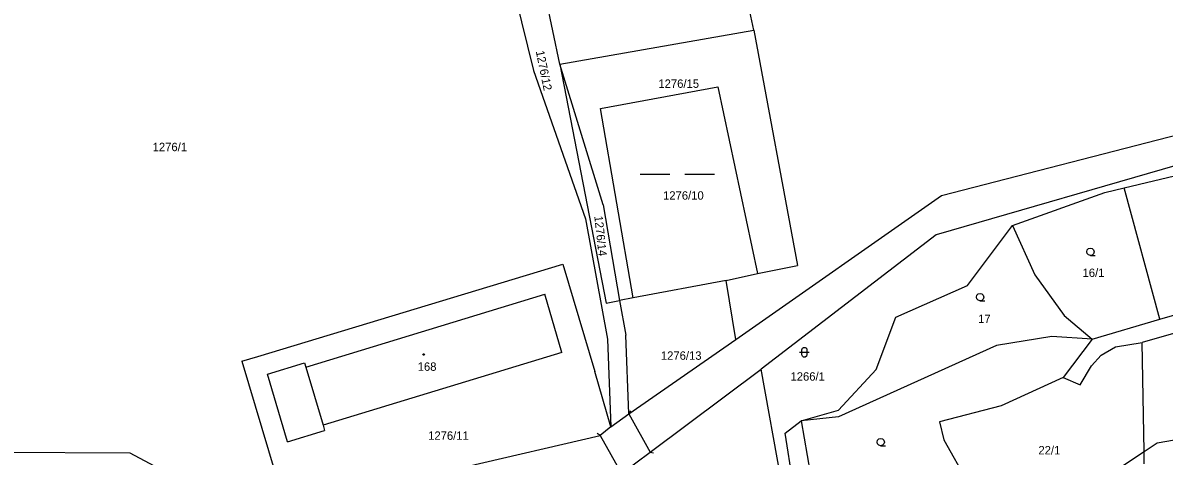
# Model space of a CAD drawing. Extents: x -799786 to -795190, y -1021716 to -1017834.
# Drawn here: x -798278.5 to -798047.9, y -1019024.7 to -1018937.1 of the extents above; entities that cross this region are included whole.
import ezdxf

# ---------------------------------------------------------------- set-up
doc = ezdxf.new("R2010")
doc.units = 0
for name, color, linetype in [('Default', 7, 'Continuous'), ('KN_HRANICE', 7, 'Continuous'), ('KN_KULTURY', 7, 'Continuous'), ('KN_PARCELY', 7, 'Continuous'), ('KN_SLUCKY', 7, 'Continuous')]:
    doc.layers.add(name, color=color, linetype=linetype)

# ---------------------------------------------------------------- blocks, each defined once
blk = doc.blocks.new('304')
at = {"layer": 'Default'}
blk.add_lwpolyline([(0, 0), (-0.38, 0.1), (-0.65, 0.37), (-0.75, 0.74), (-0.65, 1.11), (-0.38, 1.38), (-0.01, 1.48), (0.36, 1.38), (0.63, 1.11), (0.73, 0.73), (0.63, 0.35), (0.36, 0.08), (-0.02, -0.02), (0.98, -0.02)], dxfattribs=at)
blk = doc.blocks.new('316')
at = {"layer": 'Default'}
for points in [[(-1, 1), (0.27, 1), (1, 1)], [(-0.5, 1.5), (-0.4, 1.79), (-0.15, 1.97), (0.16, 1.97), (0.41, 1.79), (0.51, 1.5), (0.51, 0.5), (0.41, 0.21), (0.16, 0.03), (-0.15, 0.03), (-0.4, 0.21), (-0.5, 0.5), (-0.5, 1.5)]]:
    blk.add_lwpolyline(points, dxfattribs=at)
blk = doc.blocks.new('803')
at = {"layer": 'Default'}
for p, q in [((-7.5, 0), (-1.5, 0)), ((1.5, 0), (7.5, 0))]:
    blk.add_line(p, q, dxfattribs=at)
blk = doc.blocks.new('4201')
at = {"layer": 'Default'}
blk.add_line((0, 0), (-0.5, -0.5), dxfattribs=at)
blk = doc.blocks.new('402')
at = {"layer": 'Default'}
blk.add_lwpolyline([(0.09, 0.15), (0.18, 0), (0.09, -0.15), (-0.09, -0.15), (-0.18, 0), (-0.09, 0.15), (0.09, 0.15)], dxfattribs=at)

msp = doc.modelspace()

# ---------------------------------------------------------------- linework, layer by layer
at = {"layer": 'KN_HRANICE'}
for p, q in [((-798187.31, -1018898.18), (-798175.34, -1018946.72)), ((-798130.8, -1018938.6), (-798134.68, -1018920.36)), ((-798169.97, -1018945.48), (-798173.68, -1018927.87)), ((-798169.97, -1018945.48), (-798130.8, -1018938.6)), ((-798130.8, -1018938.6), (-798121.98, -1018986.18)), ((-798169.97, -1018945.48), (-798160.64, -1018993.78)), ((-798161.22, -1018973.87), (-798169.97, -1018945.48)), ((-798175.34, -1018946.72), (-798164.82, -1018976.7)), ((-798161.8, -1018954.45), (-798138.04, -1018950.03)), ((-798138.04, -1018950.03), (-798130.06, -1018987.79)), ((-798092.87, -1018972.02), (-798015.47, -1018951.99)), ((-798155.19, -1018992.7), (-798161.8, -1018954.45)), ((-798017.72, -1018957.95), (-798093.97, -1018979.94)), ((-798055.93, -1018970.44), (-798039.33, -1018966.51)), ((-798059.88, -1018971.37), (-798055.93, -1018970.44)), ((-798048.75, -1018997.01), (-798055.93, -1018970.44)), ((-798134.4, -1019001.1), (-798092.87, -1018972.02)), ((-798078.55, -1018978.07), (-798059.88, -1018971.37)), ((-798161.22, -1018973.87), (-798157.92, -1018993.21)), ((-798164.82, -1018976.7), (-798160.35, -1019001.01)), ((-798093.97, -1018979.94), (-798129.28, -1019007.09)), ((-798087.59, -1018990.2), (-798078.55, -1018978.07)), ((-798078.55, -1018978.07), (-798074.03, -1018988.01)), ((-798231.04, -1019004.56), (-798169.37, -1018985.89)), ((-798169.37, -1018985.89), (-798162.93, -1019007.59)), ((-798130.06, -1018987.79), (-798121.98, -1018986.18)), ((-797998.12, -1018985.97), (-798052.33, -1019001.73)), ((-798136.4, -1018989.19), (-798155.19, -1018992.7)), ((-798136.4, -1018989.19), (-798130.06, -1018987.79)), ((-798134.4, -1019001.1), (-798136.4, -1018989.19)), ((-798074.03, -1018988.01), (-798068.07, -1018996.23)), ((-798102.11, -1018996.57), (-798087.59, -1018990.2)), ((-798048.75, -1018997.01), (-798031.19, -1018991.85)), ((-798221.33, -1019006.68), (-798173.06, -1018991.96)), ((-798169.57, -1019003.7), (-798173.06, -1018991.96)), ((-798160.64, -1018993.78), (-798157.92, -1018993.21)), ((-798155.19, -1018992.7), (-798157.92, -1018993.21)), ((-798157.92, -1018993.21), (-798156.66, -1019000.22)), ((-798068.07, -1018996.23), (-798062.45, -1019001.03)), ((-798106.08, -1019007.19), (-798102.11, -1018996.57)), ((-798062.45, -1019001.03), (-798048.75, -1018997.01)), ((-798160.35, -1019001.01), (-798159.72, -1019018.72)), ((-798156.03, -1019016.14), (-798156.66, -1019000.22)), ((-798156.03, -1019016.14), (-798134.4, -1019001.1)), ((-798070.6, -1019000.48), (-798081.77, -1019002.33)), ((-798062.45, -1019001.03), (-798070.6, -1019000.48)), ((-798062.45, -1019001.03), (-798068.26, -1019008.76)), ((-798081.77, -1019002.33), (-798113.69, -1019016.72)), ((-798060.59, -1019004.24), (-798057.71, -1019002.59)), ((-798057.71, -1019002.59), (-798052.33, -1019001.73)), ((-798051.93, -1019023.72), (-798052.33, -1019001.73)), ((-798234.29, -1019005.46), (-798231.04, -1019004.56)), ((-798234.29, -1019005.46), (-798228.9, -1019023.55)), ((-798169.57, -1019003.7), (-798217.85, -1019018.39)), ((-798062.57, -1019006.43), (-798060.59, -1019004.24)), ((-798229.08, -1019008.11), (-798221.59, -1019005.82)), ((-798221.59, -1019005.82), (-798221.33, -1019006.68)), ((-798159.72, -1019018.72), (-798162.93, -1019007.59)), ((-798151.73, -1019023.84), (-798129.28, -1019007.09)), ((-798123.74, -1019037.77), (-798129.28, -1019007.09)), ((-798113.68, -1019015.35), (-798106.08, -1019007.19)), ((-798064.83, -1019010.27), (-798062.57, -1019006.43)), ((-798225.01, -1019021.78), (-798229.08, -1019008.11)), ((-798068.26, -1019008.76), (-798080.79, -1019014.52)), ((-798068.26, -1019008.76), (-798064.83, -1019010.27)), ((-798080.79, -1019014.52), (-798093.26, -1019017.74)), ((-798159.72, -1019018.72), (-798156.03, -1019016.14)), ((-798121.26, -1019017.53), (-798113.68, -1019015.35)), ((-798113.69, -1019016.72), (-798121.26, -1019017.53)), ((-798225.01, -1019021.78), (-798217.52, -1019019.49)), ((-798217.85, -1019018.39), (-798217.52, -1019019.49)), ((-798159.72, -1019018.72), (-798161.85, -1019020.48)), ((-798124.46, -1019020.04), (-798121.26, -1019017.53)), ((-798121.26, -1019017.53), (-798119.44, -1019028.03)), ((-798093.26, -1019017.74), (-798092.37, -1019021.37)), ((-798049.27, -1019021.96), (-798034.55, -1019019.48)), ((-798189.16, -1019026.83), (-798161.85, -1019020.48)), ((-798121.77, -1019037.3), (-798124.46, -1019020.04)), ((-798092.37, -1019021.37), (-798084.9, -1019034.66)), ((-798283.19, -1019023.84), (-798256.91, -1019023.98)), ((-798256.91, -1019023.98), (-798227.2, -1019039.74)), ((-798228.9, -1019023.55), (-798224.09, -1019039.53)), ((-798157.55, -1019028.18), (-798151.73, -1019023.84)), ((-798070.91, -1019036.26), (-798051.93, -1019023.72)), ((-798051.93, -1019023.72), (-798049.27, -1019021.96)), ((-798051.89, -1019026.25), (-798051.93, -1019023.72))]:
    msp.add_line(p, q, dxfattribs=at)
at = {"layer": 'KN_SLUCKY'}
for p, q in [((-798221.33, -1019006.68), (-798217.85, -1019018.39)), ((-798156.03, -1019016.14), (-798151.73, -1019023.84)), ((-798161.85, -1019020.48), (-798157.55, -1019028.18))]:
    msp.add_line(p, q, dxfattribs=at)

# ---------------------------------------------------------------- block references
at = {"layer": 'KN_KULTURY'}
for name, p in [('803', (-798146.26, -1018967.66)), ('304', (-798062.77, -1018984.11)), ('304', (-798085.08, -1018993.28)), ('316', (-798120.58, -1019004.67)), ('402', (-798197.51, -1019004.14)), ('304', (-798105.15, -1019022.56))]:
    msp.add_blockref(name, p, dxfattribs=at)
at = {"layer": 'KN_SLUCKY'}
for p, rotation in [((-798156.03, -1019016.14), -166.913223), ((-798161.85, -1019020.48), -79.88093399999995), ((-798151.73, -1019023.84), 119.40440500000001)]:
    msp.add_blockref('4201', p, dxfattribs=dict(at, rotation=rotation))

# ---------------------------------------------------------------- texts
at = {"layer": 'KN_PARCELY'}
for s, rotation, p in [('1276/12', 281.494, (-798174.86, -1018942.88)), ('1276/14', 276.223, (-798163.04, -1018976.18))]:
    msp.add_text(s, height=1.7, rotation=rotation, dxfattribs=at).set_placement(p)
for s, p in [('1276/15', (-798150.08, -1018950.25)), ('1276/1', (-798252.28, -1018963.05)), ('1276/10', (-798149.14, -1018972.85)), ('16/1', (-798064.37, -1018988.47)), ('17', (-798085.47, -1018997.77)), ('1276/13', (-798149.58, -1019005.2)), ('168', (-798198.72, -1019007.43)), ('1266/1', (-798123.39, -1019009.42)), ('1276/11', (-798196.61, -1019021.37)), ('22/1', (-798073.29, -1019024.32))]:
    msp.add_text(s, height=1.7, dxfattribs=at).set_placement(p)

doc.saveas('drawing.dxf')
